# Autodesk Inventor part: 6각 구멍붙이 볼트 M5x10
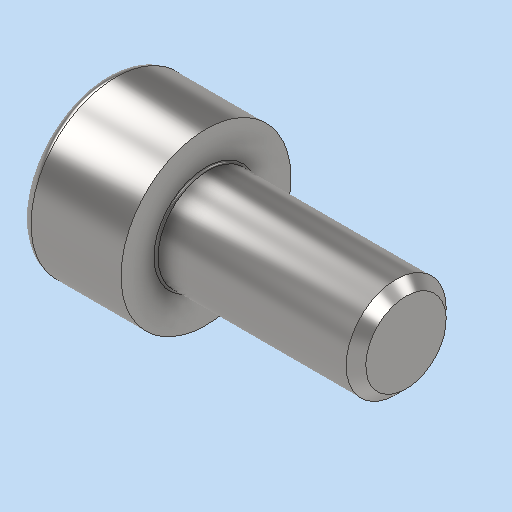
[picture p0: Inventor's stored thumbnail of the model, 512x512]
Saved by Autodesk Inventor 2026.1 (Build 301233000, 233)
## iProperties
Created: 2026-01
Part Number: 6각 구멍붙이 볼트 M5x10
Material: 강철, 연강
Description: 6각머리 태핑 나사
Document SubType Name: Modeling
Designer: PC-30
Density: 7.85 g/cm^3
Appearance: 기본값
Author: jhkim
Sending System: Autodesk Inventor 2026
Preprocessor: ST-DEVELOPER v20.1
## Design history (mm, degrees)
feature "Solid1"
node "솔리드1"
